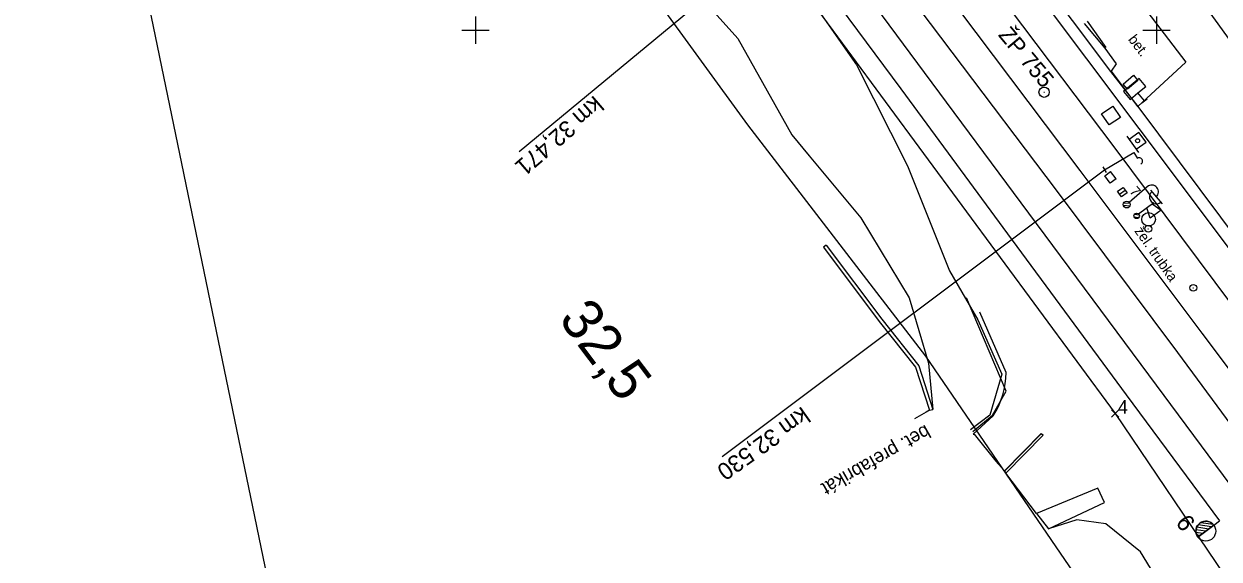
# Model space of a CAD drawing. Extents: x -804166 to -803706, y -1151030 to -1150147.
# Drawn here: x -804166.3 to -803990.8, y -1150377.7 to -1150299.1 of the extents above; entities that cross this region are included whole.
import ezdxf

# ---------------------------------------------------------------- set-up
doc = ezdxf.new("R2010")
doc.units = 0
for name, color, linetype in [('0381KM032-037P - Vrstva 1', 7, 'Continuous'), ('0381KM032-037P - Vrstva 13', 7, 'Continuous'), ('0381KM032-037P - Vrstva 16', 7, 'Continuous'), ('0381KM032-037P - Vrstva 17', 7, 'Continuous'), ('0381KM032-037P - Vrstva 2', 7, 'Continuous'), ('0381KM032-037P - Vrstva 25', 7, 'Continuous'), ('0381KM032-037P - Vrstva 3', 7, 'Continuous'), ('0381KM032-037P - Vrstva 33', 7, 'Continuous'), ('0381KM032-037P - Vrstva 4', 7, 'Continuous'), ('0381KM032-037P - Vrstva 41', 7, 'Continuous'), ('0381KM032-037P - Vrstva 43', 7, 'Continuous'), ('0381KM032-037P - Vrstva 49', 7, 'Continuous'), ('0381KM032-037P - Vrstva 50', 7, 'Continuous'), ('0381KM032-037P - Vrstva 51', 7, 'Continuous'), ('0381KM032-037P - Vrstva 7', 7, 'Continuous'), ('0381KM032-037P - Vrstva 9', 7, 'Continuous'), ('Default', 7, 'Continuous'), ('formát', 7, 'Continuous'), ('hran DP - hran DP', 7, 'Continuous'), ('krizky_1000 - Vrstva 1', 7, 'Continuous'), ('PSR_C2_2_Lomove_body_Vimperk - Vrstva 60', 7, 'Continuous'), ('PSR_C2_2_trasa_Vimperk - Kabelová trasa', 7, 'Continuous'), ('vyt_sit - stávající', 7, 'Continuous')]:
    doc.layers.add(name, color=color, linetype=linetype)

msp = doc.modelspace()

# ---------------------------------------------------------------- linework, layer by layer
at = {"layer": '0381KM032-037P - Vrstva 1'}
for points in [[(-804087.93, -1150205.28), (-804078.71, -1150215.28), (-804072.37, -1150222.52), (-804072.08, -1150222.85), (-804071.47, -1150223.58), (-804065.48, -1150230.82), (-804059.47, -1150238.51), (-804055.55, -1150243.68), (-804054.36, -1150245.27), (-804043.89, -1150259.22), (-804035.37, -1150270.61), (-804034.4, -1150271.93), (-804017.97, -1150293.92), (-804002.6, -1150314.46), (-803985.38, -1150337.43), (-803955.87, -1150376.72)], [(-804089.35, -1150206.44), (-804078.67, -1150220.7), (-804069.15, -1150233.38), (-804067.86, -1150235.11), (-804059.28, -1150246.53), (-804058.07, -1150248.16), (-804048.7, -1150260.65), (-804037.85, -1150275.13), (-804021.63, -1150296.76), (-804006.14, -1150317.34), (-803988.98, -1150340.29), (-803981.9, -1150349.73)], [(-804090.39, -1150214.38), (-804086.65, -1150219.55), (-804073.82, -1150237.11), (-804072.56, -1150238.83), (-804064.05, -1150250.31), (-804062.81, -1150251.97), (-804052.29, -1150266.05), (-804042.5, -1150279.11), (-804026.55, -1150300.33), (-804011.27, -1150320.63), (-803993.37, -1150344.49), (-803965.17, -1150382.07), (-803953.84, -1150397.19)], [(-804093.97, -1150217.42), (-804088.17, -1150225.67), (-804077.51, -1150240.28), (-804068.52, -1150252.21), (-804067.31, -1150253.81), (-804055.01, -1150270.12), (-804046.09, -1150281.93), (-804030.05, -1150303.21), (-804014.76, -1150323.52), (-803996.92, -1150347.35), (-803968.88, -1150385.42), (-803942.6, -1150419.03)], [(-804095.55, -1150218.38), (-804090.74, -1150227.08), (-804084.01, -1150238.21), (-804078.76, -1150245.78), (-804072.11, -1150254.85), (-804070.85, -1150256.55), (-804059.97, -1150271.29), (-804049.56, -1150285.37), (-804034.13, -1150306.22), (-804018.79, -1150326.86), (-804001.18, -1150350.63), (-803980.37, -1150378.68), (-803972.82, -1150388.42), (-803965.21, -1150397.6)], [(-804088.45, -1150239.45), (-804070.36, -1150264.07), (-804054.98, -1150285.05), (-804052.95, -1150287.79), (-804037.56, -1150308.64), (-804021.87, -1150329.91), (-804004.48, -1150353.56), (-803990.76, -1150372.09)]]:
    msp.add_lwpolyline(points, dxfattribs=at)
at = {"layer": '0381KM032-037P - Vrstva 13'}
for p, q in [((-804010.19, -1150298.7), (-804007.43, -1150302.56)), ((-804040.72, -1150342.79), (-804035.37, -1150349.53)), ((-804035.37, -1150349.53), (-804033.33, -1150355.83)), ((-804033.33, -1150355.83), (-804032.83, -1150355.72)), ((-804016.94, -1150359.26), (-804022.35, -1150364.74)), ((-804016.92, -1150359.32), (-804022.32, -1150364.8)), ((-804022.11, -1150365.08), (-804016.66, -1150359.51)), ((-804022.35, -1150364.74), (-804022.32, -1150364.8)), ((-804022.32, -1150364.8), (-804022.11, -1150365.08))]:
    msp.add_line(p, q, dxfattribs=at)
for points in [[(-804048.5, -1150331.59), (-804048.9, -1150331.9), (-804040.72, -1150342.79)], [(-804048.5, -1150331.59), (-804040.34, -1150342.47), (-804034.91, -1150349.29), (-804032.83, -1150355.72)], [(-804033.33, -1150355.83), (-804033.81, -1150356.11), (-804035.52, -1150357.08)], [(-804016.66, -1150359.51), (-804016.92, -1150359.32), (-804016.94, -1150359.26), (-804016.66, -1150359.51)]]:
    msp.add_lwpolyline(points, dxfattribs=at)
at = {"layer": '0381KM032-037P - Vrstva 16'}
for points in [[(-804032.64, -1150269.93), (-804033.34, -1150270.47), (-804023.51, -1150283.74), (-804006.75, -1150306.05), (-804006.63, -1150306.04)], [(-804003.99, -1150293.85), (-803995.7, -1150304.68), (-804002.75, -1150311.23), (-804006.63, -1150306.04), (-804005.86, -1150304.94), (-804007.53, -1150302.64), (-804010.58, -1150299)]]:
    msp.add_lwpolyline(points, dxfattribs=at)
at = {"layer": '0381KM032-037P - Vrstva 17'}
for p, q in [((-804026.76, -1150359.35), (-804023.62, -1150363.33)), ((-804023.62, -1150363.33), (-804022.35, -1150364.74)), ((-804017.62, -1150371.01), (-804022.11, -1150365.08)), ((-804008.64, -1150367.29), (-804017.62, -1150371.01)), ((-804007.64, -1150369.41), (-804008.64, -1150367.29)), ((-804015.88, -1150373.24), (-804007.64, -1150369.41))]:
    msp.add_line(p, q, dxfattribs=at)
for points in [[(-804026.99, -1150358.95), (-804024.09, -1150356.55), (-804022.1, -1150353.01), (-804027.89, -1150339.34)], [(-804026.92, -1150359.34), (-804026.76, -1150359.35)], [(-804017.62, -1150371.01), (-804015.88, -1150373.24)]]:
    msp.add_lwpolyline(points, dxfattribs=at)
at = {"layer": '0381KM032-037P - Vrstva 2'}
for p, q in [((-803991.59, -1150372.71), (-803993.93, -1150374.46)), ((-803993.93, -1150374.46), (-803991.59, -1150372.71)), ((-803991.93, -1150372.97), (-803993.9, -1150372.68)), ((-803991.66, -1150372.63), (-803993.54, -1150372.35)), ((-803991.59, -1150372.71), (-803990.76, -1150372.09)), ((-803991.59, -1150372.71), (-803991.59, -1150372.71)), ((-803992.78, -1150373.6), (-803994.21, -1150373.39)), ((-803993.2, -1150373.92), (-803994.21, -1150373.77)), ((-803992.35, -1150373.28), (-803994.11, -1150373.03)), ((-803993.63, -1150374.24), (-803994.1, -1150374.17))]:
    msp.add_line(p, q, dxfattribs=at)
msp.add_circle((-803992.77, -1150373.59), 1.46, dxfattribs=at)
msp.add_arc((-803992.76, -1150373.59), 1.46, 36.7889, 216.7498, dxfattribs=at)
at = {"layer": '0381KM032-037P - Vrstva 25'}
for p, q in [((-804004.01, -1150325.29), (-804001.36, -1150322.99)), ((-804000.9, -1150323.52), (-803999.2, -1150325.49)), ((-804004.81, -1150325.35), (-804003.93, -1150325.41)), ((-804004.87, -1150325.72), (-804003.91, -1150325.79))]:
    msp.add_line(p, q, dxfattribs=at)
msp.add_lwpolyline([(-804004.28, -1150308.67), (-804004.92, -1150307.91), (-804003.39, -1150306.62), (-804002.75, -1150307.38), (-804004.28, -1150308.67)], dxfattribs=at)
msp.add_circle((-804004.38, -1150325.62), 0.5, dxfattribs=at)
msp.add_circle((-804004.38, -1150325.62), 0.5, dxfattribs=at)
for centre, start, end in [((-804000.71, -1150323.75), 310.9638, 130.9638), ((-804000.06, -1150324.51), 130.2612, 311.6663)]:
    msp.add_arc(centre, 1, start, end, dxfattribs=at)
at = {"layer": '0381KM032-037P - Vrstva 3'}
for p, q in [((-804004.37, -1150315.57), (-804002.64, -1150317.96)), ((-804002.58, -1150315.01), (-804004.02, -1150316.04)), ((-804004.02, -1150316.04), (-804002.99, -1150317.49)), ((-804002.99, -1150317.49), (-804001.55, -1150316.45)), ((-804001.55, -1150316.45), (-804002.58, -1150315.01)), ((-803994.66, -1150337.85), (-803994.56, -1150337.85))]:
    msp.add_line(p, q, dxfattribs=at)
for centre, radius in [((-804002.78, -1150316.25), 0.296), ((-803994.61, -1150337.85), 0.5)]:
    msp.add_circle(centre, radius, dxfattribs=at)
at = {"layer": '0381KM032-037P - Vrstva 33'}
for p, q in [((-804000.39, -1150325.35), (-804002.63, -1150327.02)), ((-804003.25, -1150327.03), (-804002.56, -1150327.14)), ((-804000.93, -1150327.62), (-804001.43, -1150326.12)), ((-803999.33, -1150326.43), (-804000.93, -1150327.62)), ((-804000.63, -1150325.53), (-803999.33, -1150326.43)), ((-804003.3, -1150327.43), (-804002.63, -1150327.53))]:
    msp.add_line(p, q, dxfattribs=at)
msp.add_circle((-804002.93, -1150327.28), 0.401, dxfattribs=at)
msp.add_circle((-804002.93, -1150327.28), 0.401, dxfattribs=at)
at = {"layer": '0381KM032-037P - Vrstva 4'}
for points in [[(-804015.09, -1150257.7), (-804005.61, -1150276.65), (-803997.81, -1150289.61), (-803985.99, -1150305.97), (-803963.83, -1150335.54), (-803947.69, -1150357.39), (-803941.6, -1150366.02), (-803933.49, -1150379.54), (-803925.57, -1150395.83), (-803919.57, -1150411.36), (-803915.11, -1150425.7)], [(-804033.34, -1150270.47), (-804023.51, -1150283.74), (-804006.75, -1150306.05), (-804002.75, -1150311.23), (-803984.52, -1150335.59), (-803962.04, -1150365.45)]]:
    msp.add_lwpolyline(points, dxfattribs=at)
at = {"layer": '0381KM032-037P - Vrstva 41'}
for p, q in [((-804007.63, -1150320.5), (-804003.32, -1150317.97)), ((-804003.32, -1150317.97), (-804002.82, -1150318.83)), ((-804007.89, -1150320.07), (-804007.38, -1150320.93)), ((-804063.79, -1150362.63), (-804007.63, -1150320.5))]:
    msp.add_line(p, q, dxfattribs=at)
msp.add_lwpolyline([(-804006.41, -1150311.16), (-804005.3, -1150312.82), (-804006.97, -1150313.93), (-804008.08, -1150312.27), (-804006.41, -1150311.16)], dxfattribs=at)
msp.add_arc((-804002.56, -1150319.25), 0.5, 299.3257, 121.6172, dxfattribs=at)
at = {"layer": '0381KM032-037P - Vrstva 43'}
msp.add_line((-804005.93, -1150321.83), (-804006.77, -1150320.75), dxfattribs=at)
for points in [[(-804005.93, -1150321.83), (-804006.79, -1150322.47), (-804007.61, -1150321.38), (-804006.77, -1150320.75)], [(-804005.45, -1150324.07), (-804005.73, -1150323.66), (-804004.91, -1150323.09), (-804004.34, -1150323.91), (-804005.16, -1150324.48), (-804005.45, -1150324.07), (-804004.63, -1150323.5)]]:
    msp.add_lwpolyline(points, dxfattribs=at)
msp.add_circle((-804001.17, -1150327.79), 1, dxfattribs=at)
at = {"layer": '0381KM032-037P - Vrstva 49'}
for p, q in [((-804022.74, -1150350.54), (-804024.47, -1150356.54)), ((-804024.47, -1150356.54), (-804027.3, -1150358.69))]:
    msp.add_line(p, q, dxfattribs=at)
for points in [[(-804119.6, -1150227.37), (-804114.18, -1150233.24), (-804110.61, -1150241.24), (-804107.35, -1150246.09), (-804099.61, -1150256.67), (-804091.21, -1150269.57), (-804073.78, -1150287.54), (-804061.47, -1150301.24), (-804053.54, -1150315.4), (-804051.02, -1150318.44), (-804043.41, -1150327.56), (-804036.34, -1150339.31), (-804033.47, -1150348.91), (-804032.83, -1150355.72)], [(-804067.58, -1150273.2), (-804053.47, -1150291.61), (-804044.04, -1150305.1), (-804036.58, -1150319.92), (-804030.41, -1150335.37), (-804026.23, -1150342.57), (-804022.74, -1150350.54)], [(-803995.51, -1150387.87), (-804002.35, -1150376.64), (-804007.46, -1150372.51), (-804011.72, -1150371.94), (-804015.88, -1150373.24)]]:
    msp.add_lwpolyline(points, dxfattribs=at)
at = {"layer": '0381KM032-037P - Vrstva 50'}
msp.add_line((-804001.26, -1150329.18), (-804001.16, -1150329.18), dxfattribs=at)
msp.add_circle((-804001.21, -1150329.18), 0.5, dxfattribs=at)
at = {"layer": '0381KM032-037P - Vrstva 51'}
for p, q in [((-804002.16, -1150310.7), (-804001.39, -1150310.07)), ((-804022.1, -1150350.3), (-804025.97, -1150341.45)), ((-804026.92, -1150359.34), (-804023.98, -1150356.66))]:
    msp.add_line(p, q, dxfattribs=at)
for points in [[(-804015.09, -1150257.7), (-804005.61, -1150276.65), (-803997.81, -1150289.61), (-803985.99, -1150305.97), (-803963.83, -1150335.54), (-803947.69, -1150357.39), (-803941.6, -1150366.02), (-803933.49, -1150379.54), (-803925.57, -1150395.83), (-803919.57, -1150411.36), (-803915.11, -1150425.7)], [(-804001.78, -1150310.39), (-804002.73, -1150309.23), (-804001.58, -1150308.27), (-804002.53, -1150307.12), (-804004.85, -1150309.03), (-804003.89, -1150310.19), (-804002.73, -1150309.23)]]:
    msp.add_lwpolyline(points, dxfattribs=at)
msp.add_ellipse((-804033.55, -1150350.88), major_axis=(7.51, 9.2), ratio=0.940819, start_param=4.845934, end_param=5.41758, dxfattribs=at)
at = {"layer": '0381KM032-037P - Vrstva 9'}
msp.add_line((-804041.91, -1150275.08), (-804093.56, -1150317.87), dxfattribs=at)
at = {"layer": 'formát'}
msp.add_line((-804166.3, -1150207.4), (-804123.84, -1150413.06), dxfattribs=at)
at = {"layer": 'hran DP - hran DP'}
for p, q in [((-804060.01, -1150313.9), (-804081.21, -1150284.7)), ((-804033.86, -1150347.88), (-804060.01, -1150313.9)), ((-804004.05, -1150391.51), (-804033.86, -1150347.88))]:
    msp.add_line(p, q, dxfattribs=at)
at = {"layer": 'krizky_1000 - Vrstva 1'}
for points in [[(-804100, -1150298), (-804100, -1150302)], [(-804000, -1150298), (-804000, -1150302)], [(-804102, -1150300), (-804098, -1150300)], [(-804002, -1150300), (-803998, -1150300)]]:
    msp.add_lwpolyline(points, dxfattribs=at)
at = {"layer": 'PSR_C2_2_Lomove_body_Vimperk - Vrstva 60'}
for p, q in [((-804006.62, -1150356.85), (-804005.52, -1150355.75)), ((-804005.52, -1150356.85), (-804006.62, -1150355.75))]:
    msp.add_line(p, q, dxfattribs=at)
at = {"layer": 'PSR_C2_2_trasa_Vimperk - Kabelová trasa'}
msp.add_line((-804077.48, -1150259.34), (-804006.07, -1150356.3), dxfattribs=at)
msp.add_lwpolyline([(-804006.07, -1150356.3), (-803990.08, -1150380.01), (-803977.68, -1150395.4)], dxfattribs=at)
at = {"layer": 'vyt_sit - stávající'}
msp.add_line((-804016.56, -1150309.12), (-804016.46, -1150309.12), dxfattribs=at)
msp.add_circle((-804016.51, -1150309.12), 0.756, dxfattribs=at)

# ---------------------------------------------------------------- texts
at = {"layer": '0381KM032-037P - Vrstva 13'}
msp.add_text('bet. prefabrikát', height=2, rotation=209.6616, dxfattribs=at).set_placement((-804033.92, -1150357.9))
at = {"layer": '0381KM032-037P - Vrstva 16'}
msp.add_text('bet.', height=1.5, rotation=307.4446, dxfattribs=at).set_placement((-804004.25, -1150301.38))
at = {"layer": '0381KM032-037P - Vrstva 2'}
msp.add_text('6', height=2.5, rotation=306.7693, dxfattribs=at).set_placement((-803997.29, -1150372.37))
at = {"layer": '0381KM032-037P - Vrstva 25'}
msp.add_text('7', height=1.5, rotation=310.9638, dxfattribs=at).set_placement((-804004.06, -1150323.75))
at = {"layer": '0381KM032-037P - Vrstva 41'}
msp.add_text('km 32,530', height=2.5, rotation=215.4715, dxfattribs=at).set_placement((-804052.06, -1150355.2))
at = {"layer": '0381KM032-037P - Vrstva 50'}
msp.add_text('žel. trubka', height=1.5, rotation=305, dxfattribs=at).set_placement((-804003.31, -1150329.5))
at = {"layer": '0381KM032-037P - Vrstva 7'}
msp.add_text('32,5', height=6, rotation=306.9651, dxfattribs=at).set_placement((-804087.92, -1150342.46))
at = {"layer": '0381KM032-037P - Vrstva 9'}
msp.add_text('km 32,471', height=2.5, rotation=220.7607, dxfattribs=at).set_placement((-804082.58, -1150309.5))
at = {"layer": 'Default'}
msp.add_text('4', height=2, dxfattribs=at).set_placement((-804005.69, -1150356.35))
at = {"layer": 'vyt_sit - stávající'}
msp.add_text('ŽP 755', height=2.4, rotation=310, dxfattribs=at).set_placement((-804023.35, -1150300.75))

doc.saveas('drawing.dxf')
